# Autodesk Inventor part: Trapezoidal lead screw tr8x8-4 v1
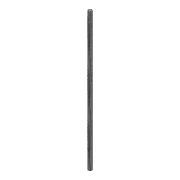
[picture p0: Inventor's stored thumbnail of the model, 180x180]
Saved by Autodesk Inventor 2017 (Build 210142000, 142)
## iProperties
Created: 2018-08
Part Number: Trapezoidal lead screw tr8x8-4 v1
Material: Stainless Steel AISI 304
Document SubType Name: Modeling
Designer: JK
Density: 8 g/cm^3
Appearance: Chrome - Satin
Author: JK
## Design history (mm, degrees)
feature "Body1"
body "Solid1"
